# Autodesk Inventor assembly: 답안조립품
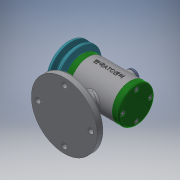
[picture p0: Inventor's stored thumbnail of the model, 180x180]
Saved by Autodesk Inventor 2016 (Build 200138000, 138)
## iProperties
Created: 2018-12
Part Number: 답안조립품
Document SubType Name: Assembly
Designer: Administrator
Author: Administrator
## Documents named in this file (15)
- C:\Users\Administrator\Desktop\이종현 12 22\481208V1019\답안조립품.iam
- C:\Users\Administrator\Desktop\이종현 12 22\481208V1019\부품1.ipt
- C:\Users\Administrator\Desktop\이종현 12 22\481208V1019\축.ipt
- C:\Users\Administrator\Desktop\이종현 12 22\481208V1019\키 3 x 3 x 12.ipt
- C:\Users\Administrator\Desktop\이종현 12 22\481208V1019\V벨트풀리.ipt
- C:\Users\Administrator\Desktop\이종현 12 22\481208V1019\너트 M8.ipt
- 너트 M8.ipt
- C:\Users\Administrator\Desktop\이종현 12 22\481208V1019\스프링와셔 8.ipt
- C:\Users\Administrator\Desktop\이종현 12 22\481208V1019\와셔 8x17.ipt
- C:\Users\Administrator\Desktop\이종현 12 22\481208V1019\베어링 15 x 32 x 9.ipt
- C:\Users\Administrator\Desktop\이종현 12 22\481208V1019\볼트 M4 x 12.ipt
- C:\Users\Administrator\Desktop\이종현 12 22\481208V1019\앞커버.ipt
- C:\Users\Administrator\Desktop\이종현 12 22\481208V1019\오일 실 15 25 7.ipt
- C:\Users\Administrator\Desktop\이종현 12 22\481208V1019\뒤커버.ipt
- C:\Users\Administrator\Desktop\이종현 12 22\481208V1019\고무캡.ipt
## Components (2 placed, 2 different names)
1. V벨트풀리:1 — 각도:2
2. 고무캡:1
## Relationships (1: Angle 1)
- 각도:2 [Angle]: V벨트풀리:1
